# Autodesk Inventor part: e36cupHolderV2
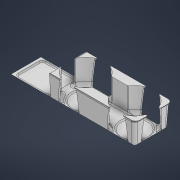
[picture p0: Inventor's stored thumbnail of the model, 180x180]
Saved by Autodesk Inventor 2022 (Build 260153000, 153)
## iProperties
Created: 2024-06
Part Number: e36cupHolderV2
Material: Všeobecné
Document SubType Name: Modeling
Designer: FIJI
Density: 1 g/cm^3
Appearance: Výchozí
Author: FIJI
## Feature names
1. Tažení1
2. Zaoblení2 [Fillet]
3. Zaoblení3 [Fillet]
4. Vysunutí3 [Extrusion]
5. Zaoblení4 [Fillet]
6. Vysunutí4 [Extrusion]
7. Vysunutí6 [Extrusion]
8. Zaoblení7 [Fillet]
9. Zaoblení8 [Fillet]
10. Vysunutí7 [Extrusion]
11. Vysunutí8 [Extrusion]
12. Vysunutí9 [Extrusion]
13. Zaoblení9 [Fillet]
## Parameters: d0 = 236.8 mm, d1 = 67.6 mm, d22 = 30.5 mm, d24 = 48 mm, d25 = 0, d26 = 0, d27 = 0.8 mm, d28 = 0.8 mm, d29 = 6 mm, d30 = 6 mm, d31 = 7 mm, d32 = 0.8 mm, d33 = 69 mm, d34 = 69 mm, d35 = 33.8 mm, d36 = 33.8 mm, d37 = 33.8 mm, d39 = 44 mm, d40 = 0, d41 = 5.8 mm, d42 = 1 mm, d43 = 13.82896 mm, d44 = 17.5 mm, d45 = 52 mm, d46 = 52 mm, d47 = 6 mm, d48 = 4.18551 mm, d49 = 4.8 mm, d50 = 4.8 mm, d51 = 4.8 mm, d54 = 2 mm, d55 = 0, d56 = 60.37101 mm, d63 = 1.8 mm, d64 = 8 mm, d65 = 0.8 mm, d66 = 0, d71 = 13.82896 mm, d72 = 6.91448 mm, d73 = 1.8 mm, d74 = 1 mm, d75 = 5.8 mm, d76 = 2.4 mm, d77 = 2.4 mm, d78 = 2 mm, d79 = 2.4 mm, d80 = 0, d81 = 0, d82 = 1 mm, d86 = 1.4 mm, d87 = 45 deg, d88 = 0, d89 = 0, d90 = 45 deg, d91 = 0, d92 = 0, d93 = 4 mm
